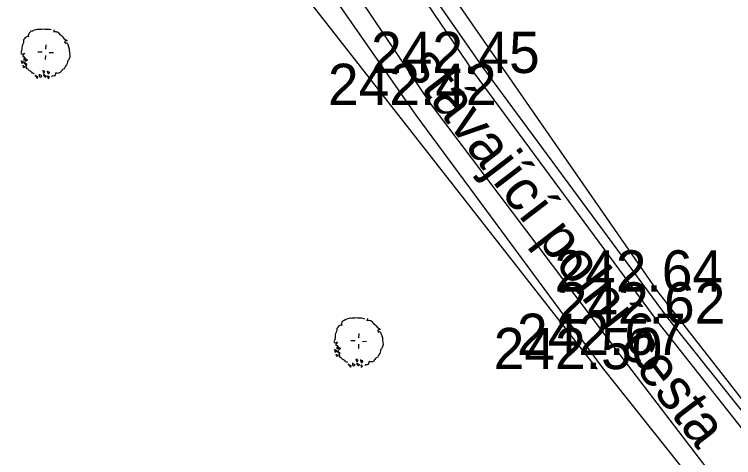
# Model space of a CAD drawing. Extents: x -601754 to -601440, y -1201912 to -1200862.
# Drawn here: x -601508.22 to -601473.34, y -1201687.06 to -1201665.57 of the extents above; entities that cross this region are included whole.
import ezdxf

# ---------------------------------------------------------------- set-up
doc = ezdxf.new("R2010")
doc.units = 0
for name, color, linetype in [('Hranice parcel', 7, 'Continuous'), ('u_hrany', 7, 'Continuous'), ('u_S0 02', 7, 'Continuous'), ('u_vysadba', 7, 'Continuous'), ('u_vyska', 7, 'Continuous')]:
    doc.layers.add(name, color=color, linetype=linetype)

msp = doc.modelspace()

# ---------------------------------------------------------------- linework, layer by layer
at = {"layer": 'Hranice parcel'}
for points in [[(-601518.5, -1201574.62), (-601510.22, -1201581.07), (-601510.94, -1201612.53), (-601510.72, -1201619.53), (-601510.05, -1201624.75), (-601508.24, -1201633.75), (-601505.86, -1201640.82), (-601502.47, -1201648.58), (-601498.5, -1201656.04), (-601493.62, -1201663.46), (-601488.75, -1201670.45), (-601479.72, -1201682.69), (-601461.88, -1201705.09), (-601454.585, -1201713.629)], [(-601460.43, -1201700.48), (-601476.54, -1201680.26), (-601485.5, -1201668.12), (-601490.31, -1201661.22), (-601495.06, -1201653.99), (-601498.9, -1201646.76), (-601502.13, -1201639.37), (-601504.35, -1201632.81), (-601505.66, -1201626.3)]]:
    msp.add_lwpolyline(points, dxfattribs=at)
at = {"layer": 'u_hrany'}
for points in [[(-601460.33, -1201700.35), (-601477.02, -1201679.01), (-601490.59, -1201659.41), (-601493.47, -1201654.35), (-601500.4, -1201641.28), (-601502.56, -1201635.52), (-601504.77, -1201626.02), (-601500.77, -1201618.77)], [(-601454.585, -1201708.29), (-601460.41, -1201701.5), (-601476.94, -1201680.56), (-601485.91, -1201668.41), (-601495.49, -1201654.25), (-601502.92, -1201639.69), (-601504.84, -1201632.93)], [(-601507.17, -1201633.88), (-601501.63, -1201648), (-601497.69, -1201655.55), (-601488, -1201669.96), (-601478.86, -1201682.08), (-601462.72, -1201703.16), (-601454.585, -1201712.627)], [(-601502.92, -1201648.81), (-601499.15, -1201656.12), (-601494.42, -1201664.28), (-601479.96, -1201682.77)]]:
    msp.add_lwpolyline(points, dxfattribs=at)
at = {"layer": 'u_vysadba'}
for points in [[(-601507.697, -1201666.71), (-601507.696, -1201666.68), (-601507.636, -1201666.654), (-601507.606, -1201666.641), (-601507.576, -1201666.628), (-601507.546, -1201666.63), (-601507.517, -1201666.631), (-601507.53, -1201666.601), (-601507.543, -1201666.571), (-601507.526, -1201666.528), (-601507.51, -1201666.485), (-601507.478, -1201666.443), (-601507.447, -1201666.415), (-601507.417, -1201666.388), (-601507.371, -1201666.361), (-601507.327, -1201666.363), (-601507.297, -1201666.335), (-601507.222, -1201666.31), (-601507.163, -1201666.299), (-601507.118, -1201666.286), (-601507.06, -1201666.289), (-601507.015, -1201666.277), (-601506.972, -1201666.279), (-601506.899, -1201666.283), (-601506.825, -1201666.272), (-601506.752, -1201666.276), (-601506.664, -1201666.281), (-601506.577, -1201666.286), (-601506.504, -1201666.289), (-601506.46, -1201666.306), (-601506.432, -1201666.322)], [(-601506.285, -1201666.316), (-601506.301, -1201666.344), (-601506.303, -1201666.373), (-601506.319, -1201666.402), (-601506.275, -1201666.389), (-601506.245, -1201666.391), (-601506.216, -1201666.392), (-601506.173, -1201666.409), (-601506.129, -1201666.412), (-601506.087, -1201666.443), (-601506.059, -1201666.474), (-601506.032, -1201666.519), (-601505.99, -1201666.551), (-601505.934, -1201666.598), (-601505.893, -1201666.644), (-601505.865, -1201666.675), (-601505.824, -1201666.735), (-601505.767, -1201666.768), (-601505.725, -1201666.799), (-601505.682, -1201666.816), (-601505.684, -1201666.845)], [(-601507.697, -1201666.71), (-601507.698, -1201666.724), (-601507.744, -1201666.766), (-601507.775, -1201666.793), (-601507.777, -1201666.837), (-601507.779, -1201666.881), (-601507.782, -1201666.939), (-601507.799, -1201666.982), (-601507.816, -1201667.011), (-601507.832, -1201667.039), (-601507.849, -1201667.097), (-601507.851, -1201667.126), (-601507.854, -1201667.184), (-601507.856, -1201667.228), (-601507.858, -1201667.258), (-601507.876, -1201667.33), (-601507.893, -1201667.373), (-601507.896, -1201667.417), (-601507.912, -1201667.445), (-601507.899, -1201667.475), (-601507.856, -1201667.492), (-601507.766, -1201667.467), (-601507.736, -1201667.454), (-601507.769, -1201667.511), (-601507.8, -1201667.539), (-601507.816, -1201667.567), (-601507.818, -1201667.611), (-601507.789, -1201667.613), (-601507.745, -1201667.615), (-601507.732, -1201667.645), (-601507.749, -1201667.688), (-601507.765, -1201667.716), (-601507.767, -1201667.76), (-601507.77, -1201667.804)], [(-601506.698, -1201667.251), (-601506.687, -1201667.047)], [(-601505.684, -1201666.845), (-601505.728, -1201666.858), (-601505.773, -1201666.87), (-601505.789, -1201666.898), (-601505.776, -1201666.928), (-601505.749, -1201666.974), (-601505.719, -1201666.961), (-601505.674, -1201666.948), (-601505.647, -1201666.979), (-601505.634, -1201667.009), (-601505.635, -1201667.038), (-601505.609, -1201667.098), (-601505.597, -1201667.143), (-601505.585, -1201667.187), (-601505.558, -1201667.233), (-601505.559, -1201667.262), (-601505.561, -1201667.306), (-601505.563, -1201667.335), (-601505.551, -1201667.379), (-601505.539, -1201667.439), (-601505.542, -1201667.497), (-601505.531, -1201667.556), (-601505.532, -1201667.585), (-601505.534, -1201667.615), (-601505.536, -1201667.658), (-601505.567, -1201667.686), (-601505.568, -1201667.715), (-601505.585, -1201667.758), (-601505.602, -1201667.787), (-601505.648, -1201667.828), (-601505.651, -1201667.887), (-601505.668, -1201667.944), (-601505.687, -1201668.016), (-601505.734, -1201668.073), (-601505.767, -1201668.144), (-601505.799, -1201668.201), (-601505.859, -1201668.227), (-601505.89, -1201668.255), (-601505.936, -1201668.296), (-601505.967, -1201668.338), (-601505.984, -1201668.381), (-601506.044, -1201668.408), (-601506.089, -1201668.42), (-601506.119, -1201668.433), (-601506.162, -1201668.416), (-601506.205, -1201668.399), (-601506.222, -1201668.442), (-601506.24, -1201668.5), (-601506.256, -1201668.543), (-601506.301, -1201668.555), (-601506.345, -1201668.553)], [(-601506.881, -1201667.402), (-601507.086, -1201667.392)], [(-601506.531, -1201667.421), (-601506.326, -1201667.417)], [(-601507.901, -1201667.797), (-601507.888, -1201667.827), (-601507.876, -1201667.872), (-601507.863, -1201667.902), (-601507.864, -1201667.931), (-601507.836, -1201667.947), (-601507.805, -1201667.919), (-601507.759, -1201667.878), (-601507.788, -1201667.876), (-601507.83, -1201667.845), (-601507.873, -1201667.828)], [(-601507.743, -1201667.864), (-601507.702, -1201667.91), (-601507.66, -1201667.956), (-601507.618, -1201667.988)], [(-601507.719, -1201667.675), (-601507.721, -1201667.719), (-601507.708, -1201667.749), (-601507.696, -1201667.793), (-601507.683, -1201667.823), (-601507.654, -1201667.825), (-601507.637, -1201667.796), (-601507.577, -1201667.77), (-601507.62, -1201667.753), (-601507.649, -1201667.737), (-601507.706, -1201667.705)], [(-601506.714, -1201667.558), (-601506.725, -1201667.762)], [(-601507.811, -1201668.036), (-601507.801, -1201668.124), (-601507.757, -1201668.127), (-601507.728, -1201668.128), (-601507.684, -1201668.116), (-601507.741, -1201668.098), (-601507.785, -1201668.096), (-601507.798, -1201668.066)], [(-601507.618, -1201667.988), (-601507.647, -1201667.986), (-601507.677, -1201667.985), (-601507.706, -1201667.983), (-601507.719, -1201667.953), (-601507.717, -1201667.924), (-601507.73, -1201667.894)], [(-601507.247, -1201668.447), (-601507.29, -1201668.43), (-601507.319, -1201668.413), (-601507.348, -1201668.412), (-601507.375, -1201668.367), (-601507.403, -1201668.35), (-601507.445, -1201668.319), (-601507.488, -1201668.302), (-601507.53, -1201668.256), (-601507.558, -1201668.225), (-601507.629, -1201668.192), (-601507.627, -1201668.148), (-601507.624, -1201668.104), (-601507.637, -1201668.074), (-601507.666, -1201668.058), (-601507.634, -1201668.016), (-601507.605, -1201668.018)], [(-601507.236, -1201668.506), (-601507.14, -1201668.628), (-601507.113, -1201668.673), (-601507.081, -1201668.631), (-601507.08, -1201668.602), (-601507.108, -1201668.586), (-601507.151, -1201668.569), (-601507.18, -1201668.553), (-601507.208, -1201668.536)], [(-601507.013, -1201668.459), (-601507.017, -1201668.532), (-601507.005, -1201668.576), (-601506.977, -1201668.607), (-601506.918, -1201668.596), (-601506.887, -1201668.568), (-601506.901, -1201668.538), (-601506.944, -1201668.521), (-601506.987, -1201668.504)], [(-601506.843, -1201668.278), (-601506.832, -1201668.351), (-601506.805, -1201668.397), (-601506.761, -1201668.384), (-601506.759, -1201668.355), (-601506.758, -1201668.326), (-601506.801, -1201668.309), (-601506.829, -1201668.293)], [(-601506.808, -1201668.455), (-601506.725, -1201668.533), (-601506.696, -1201668.549), (-601506.683, -1201668.579), (-601506.714, -1201668.606), (-601506.743, -1201668.605), (-601506.756, -1201668.575), (-601506.783, -1201668.53), (-601506.811, -1201668.499)], [(-601506.64, -1201668.318), (-601506.614, -1201668.377), (-601506.602, -1201668.422), (-601506.574, -1201668.453), (-601506.544, -1201668.44), (-601506.512, -1201668.397), (-601506.511, -1201668.368), (-601506.555, -1201668.366), (-601506.583, -1201668.35), (-601506.612, -1201668.334), (-601506.641, -1201668.332)], [(-601506.609, -1201668.568), (-601506.599, -1201668.642), (-601506.585, -1201668.672), (-601506.555, -1201668.659), (-601506.524, -1201668.617), (-601506.552, -1201668.586), (-601506.58, -1201668.57), (-601506.609, -1201668.568)], [(-601506.345, -1201668.553), (-601506.389, -1201668.565), (-601506.42, -1201668.593)], [(-601492.506, -1201680.711), (-601492.505, -1201680.682), (-601492.445, -1201680.656), (-601492.415, -1201680.643), (-601492.385, -1201680.63), (-601492.356, -1201680.632), (-601492.326, -1201680.633), (-601492.339, -1201680.603), (-601492.352, -1201680.573), (-601492.336, -1201680.53), (-601492.319, -1201680.487), (-601492.287, -1201680.445), (-601492.256, -1201680.417), (-601492.226, -1201680.39), (-601492.18, -1201680.363), (-601492.136, -1201680.365), (-601492.106, -1201680.337), (-601492.031, -1201680.312), (-601491.972, -1201680.3), (-601491.927, -1201680.288), (-601491.869, -1201680.291), (-601491.824, -1201680.279), (-601491.781, -1201680.281), (-601491.708, -1201680.285), (-601491.634, -1201680.274), (-601491.561, -1201680.278), (-601491.473, -1201680.283), (-601491.386, -1201680.287), (-601491.313, -1201680.291), (-601491.27, -1201680.308), (-601491.241, -1201680.324)], [(-601491.094, -1201680.318), (-601491.111, -1201680.346), (-601491.112, -1201680.375), (-601491.128, -1201680.404), (-601491.084, -1201680.391), (-601491.054, -1201680.393), (-601491.025, -1201680.394), (-601490.982, -1201680.411), (-601490.938, -1201680.414), (-601490.896, -1201680.445), (-601490.868, -1201680.476), (-601490.842, -1201680.521), (-601490.799, -1201680.553), (-601490.743, -1201680.6), (-601490.702, -1201680.646), (-601490.674, -1201680.676), (-601490.633, -1201680.737), (-601490.576, -1201680.77), (-601490.534, -1201680.801), (-601490.491, -1201680.818), (-601490.493, -1201680.847)], [(-601492.506, -1201680.711), (-601492.507, -1201680.726), (-601492.553, -1201680.768), (-601492.584, -1201680.795), (-601492.586, -1201680.839), (-601492.588, -1201680.883), (-601492.592, -1201680.941), (-601492.608, -1201680.984), (-601492.625, -1201681.013), (-601492.641, -1201681.041), (-601492.658, -1201681.099), (-601492.66, -1201681.128), (-601492.663, -1201681.186), (-601492.665, -1201681.23), (-601492.667, -1201681.259), (-601492.685, -1201681.332), (-601492.702, -1201681.375), (-601492.705, -1201681.418), (-601492.721, -1201681.447), (-601492.708, -1201681.477), (-601492.665, -1201681.494), (-601492.576, -1201681.469), (-601492.546, -1201681.456), (-601492.578, -1201681.513), (-601492.609, -1201681.541), (-601492.625, -1201681.569), (-601492.627, -1201681.613), (-601492.598, -1201681.614), (-601492.554, -1201681.617), (-601492.541, -1201681.647), (-601492.558, -1201681.69), (-601492.574, -1201681.718), (-601492.576, -1201681.762), (-601492.579, -1201681.806)], [(-601491.507, -1201681.253), (-601491.496, -1201681.049)], [(-601490.493, -1201680.847), (-601490.537, -1201680.859), (-601490.582, -1201680.872), (-601490.598, -1201680.9), (-601490.585, -1201680.93), (-601490.558, -1201680.975), (-601490.528, -1201680.962), (-601490.484, -1201680.95), (-601490.456, -1201680.981), (-601490.443, -1201681.011), (-601490.444, -1201681.04), (-601490.418, -1201681.1), (-601490.406, -1201681.145), (-601490.394, -1201681.189), (-601490.367, -1201681.235), (-601490.368, -1201681.264), (-601490.371, -1201681.308), (-601490.372, -1201681.337), (-601490.36, -1201681.381), (-601490.348, -1201681.44), (-601490.351, -1201681.499), (-601490.34, -1201681.558), (-601490.341, -1201681.587), (-601490.343, -1201681.616), (-601490.345, -1201681.66), (-601490.376, -1201681.688), (-601490.378, -1201681.717), (-601490.395, -1201681.76), (-601490.411, -1201681.789), (-601490.457, -1201681.83), (-601490.46, -1201681.889), (-601490.478, -1201681.946), (-601490.496, -1201682.018), (-601490.543, -1201682.074), (-601490.576, -1201682.146), (-601490.608, -1201682.203), (-601490.668, -1201682.229), (-601490.699, -1201682.257), (-601490.745, -1201682.298), (-601490.777, -1201682.34), (-601490.794, -1201682.383), (-601490.853, -1201682.409), (-601490.898, -1201682.422), (-601490.928, -1201682.435), (-601490.971, -1201682.418), (-601491.014, -1201682.401), (-601491.031, -1201682.444), (-601491.049, -1201682.502), (-601491.066, -1201682.545), (-601491.11, -1201682.557), (-601491.154, -1201682.555)], [(-601491.69, -1201681.404), (-601491.895, -1201681.394)], [(-601491.34, -1201681.423), (-601491.135, -1201681.419)], [(-601492.71, -1201681.799), (-601492.697, -1201681.829), (-601492.685, -1201681.873), (-601492.672, -1201681.903), (-601492.673, -1201681.933), (-601492.645, -1201681.949), (-601492.614, -1201681.921), (-601492.568, -1201681.88), (-601492.597, -1201681.878), (-601492.639, -1201681.847), (-601492.682, -1201681.83)], [(-601492.528, -1201681.677), (-601492.53, -1201681.721), (-601492.517, -1201681.751), (-601492.505, -1201681.795), (-601492.492, -1201681.825), (-601492.463, -1201681.827), (-601492.446, -1201681.798), (-601492.387, -1201681.772), (-601492.43, -1201681.755), (-601492.458, -1201681.739), (-601492.515, -1201681.707)], [(-601491.523, -1201681.56), (-601491.534, -1201681.764)], [(-601492.62, -1201682.038), (-601492.61, -1201682.126), (-601492.566, -1201682.129), (-601492.537, -1201682.13), (-601492.493, -1201682.118), (-601492.55, -1201682.1), (-601492.594, -1201682.098), (-601492.607, -1201682.068)], [(-601492.553, -1201681.866), (-601492.511, -1201681.912), (-601492.47, -1201681.958), (-601492.427, -1201681.99)], [(-601492.427, -1201681.99), (-601492.457, -1201681.988), (-601492.486, -1201681.986), (-601492.515, -1201681.985), (-601492.528, -1201681.955), (-601492.526, -1201681.926), (-601492.54, -1201681.896)], [(-601492.056, -1201682.448), (-601492.099, -1201682.432), (-601492.128, -1201682.415), (-601492.157, -1201682.414), (-601492.184, -1201682.368), (-601492.212, -1201682.352), (-601492.254, -1201682.321), (-601492.298, -1201682.304), (-601492.339, -1201682.258), (-601492.367, -1201682.227), (-601492.438, -1201682.194), (-601492.436, -1201682.15), (-601492.433, -1201682.106), (-601492.447, -1201682.076), (-601492.475, -1201682.06), (-601492.443, -1201682.018), (-601492.414, -1201682.02)], [(-601492.045, -1201682.508), (-601491.949, -1201682.63), (-601491.922, -1201682.675), (-601491.89, -1201682.633), (-601491.889, -1201682.604), (-601491.917, -1201682.588), (-601491.96, -1201682.571), (-601491.989, -1201682.555), (-601492.017, -1201682.538)], [(-601491.823, -1201682.461), (-601491.826, -1201682.534), (-601491.814, -1201682.578), (-601491.786, -1201682.609), (-601491.727, -1201682.598), (-601491.697, -1201682.57), (-601491.71, -1201682.54), (-601491.753, -1201682.523), (-601491.796, -1201682.506)], [(-601491.652, -1201682.279), (-601491.641, -1201682.353), (-601491.614, -1201682.399), (-601491.57, -1201682.386), (-601491.568, -1201682.357), (-601491.567, -1201682.328), (-601491.61, -1201682.311), (-601491.638, -1201682.295)], [(-601491.617, -1201682.457), (-601491.534, -1201682.535), (-601491.505, -1201682.551), (-601491.492, -1201682.581), (-601491.523, -1201682.608), (-601491.552, -1201682.607), (-601491.565, -1201682.577), (-601491.592, -1201682.532), (-601491.62, -1201682.501)], [(-601491.449, -1201682.319), (-601491.423, -1201682.379), (-601491.411, -1201682.424), (-601491.383, -1201682.455), (-601491.353, -1201682.442), (-601491.321, -1201682.399), (-601491.32, -1201682.37), (-601491.364, -1201682.368), (-601491.392, -1201682.352), (-601491.421, -1201682.336), (-601491.45, -1201682.334)], [(-601491.418, -1201682.57), (-601491.408, -1201682.644), (-601491.395, -1201682.674), (-601491.365, -1201682.661), (-601491.333, -1201682.618), (-601491.361, -1201682.588), (-601491.389, -1201682.572), (-601491.418, -1201682.57)], [(-601491.154, -1201682.555), (-601491.199, -1201682.567), (-601491.229, -1201682.595)]]:
    msp.add_lwpolyline(points, dxfattribs=at)

# ---------------------------------------------------------------- texts
at = {"layer": 'u_S0 02'}
msp.add_text('stávající polní cesta ', height=2, rotation=307.4888, dxfattribs=at).set_placement((-601489.357, -1201668.078))
at = {"layer": 'u_vyska'}
for s, p in [('242.45', (-601490.922, -1201668.41)), ('242.42', (-601493.012, -1201669.96)), ('242.64', (-601482.027, -1201679.01)), ('242.62', (-601481.919, -1201680.56)), ('242.67', (-601483.844, -1201682.08)), ('242.50', (-601484.975, -1201682.77))]:
    msp.add_text(s, height=2, dxfattribs=at).set_placement(p)

doc.saveas('drawing.dxf')
